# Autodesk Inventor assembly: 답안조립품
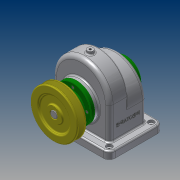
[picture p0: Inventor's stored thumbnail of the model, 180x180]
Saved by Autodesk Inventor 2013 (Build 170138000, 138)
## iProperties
Created: 2017-11
Part Number: 답안조립품
Document SubType Name: Assembly
Designer: Administrator
Author: Administrator
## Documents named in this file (14)
- C:\Users\Administrator\Desktop\471108V1024\답안조립품.iam
- C:\Users\Administrator\Desktop\471108V1024\본체.ipt
- C:\Users\Administrator\Desktop\471108V1024\V-벨트풀리.ipt
- C:\Users\Administrator\Desktop\471108V1024\뒤커버.ipt
- C:\Users\Administrator\Desktop\471108V1024\멈춤나사 - M4 x 10.ipt
- 멈춤나사 - M4 x 10.ipt
- C:\Users\Administrator\Desktop\471108V1024\베어링 6002.ipt
- C:\Users\Administrator\Desktop\471108V1024\볼트 M3 x 8.ipt
- C:\Users\Administrator\Desktop\471108V1024\스퍼기어.ipt
- C:\Users\Administrator\Desktop\471108V1024\앞커버.ipt
- C:\Users\Administrator\Desktop\471108V1024\오일 실 15 30 7.ipt
- C:\Users\Administrator\Desktop\471108V1024\축.ipt
- C:\Users\Administrator\Desktop\471108V1024\키 - 5 x 5 x 18.ipt
- C:\Users\Administrator\Desktop\471108V1024\키 - 6 x 6 x 22.ipt
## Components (1 placed, 1 different names)
1. V-벨트풀리:1 — 각도:3
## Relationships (1: Angle 1)
- 각도:3 [Angle]: V-벨트풀리:1
